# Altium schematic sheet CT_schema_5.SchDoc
size 368 x 245 mm
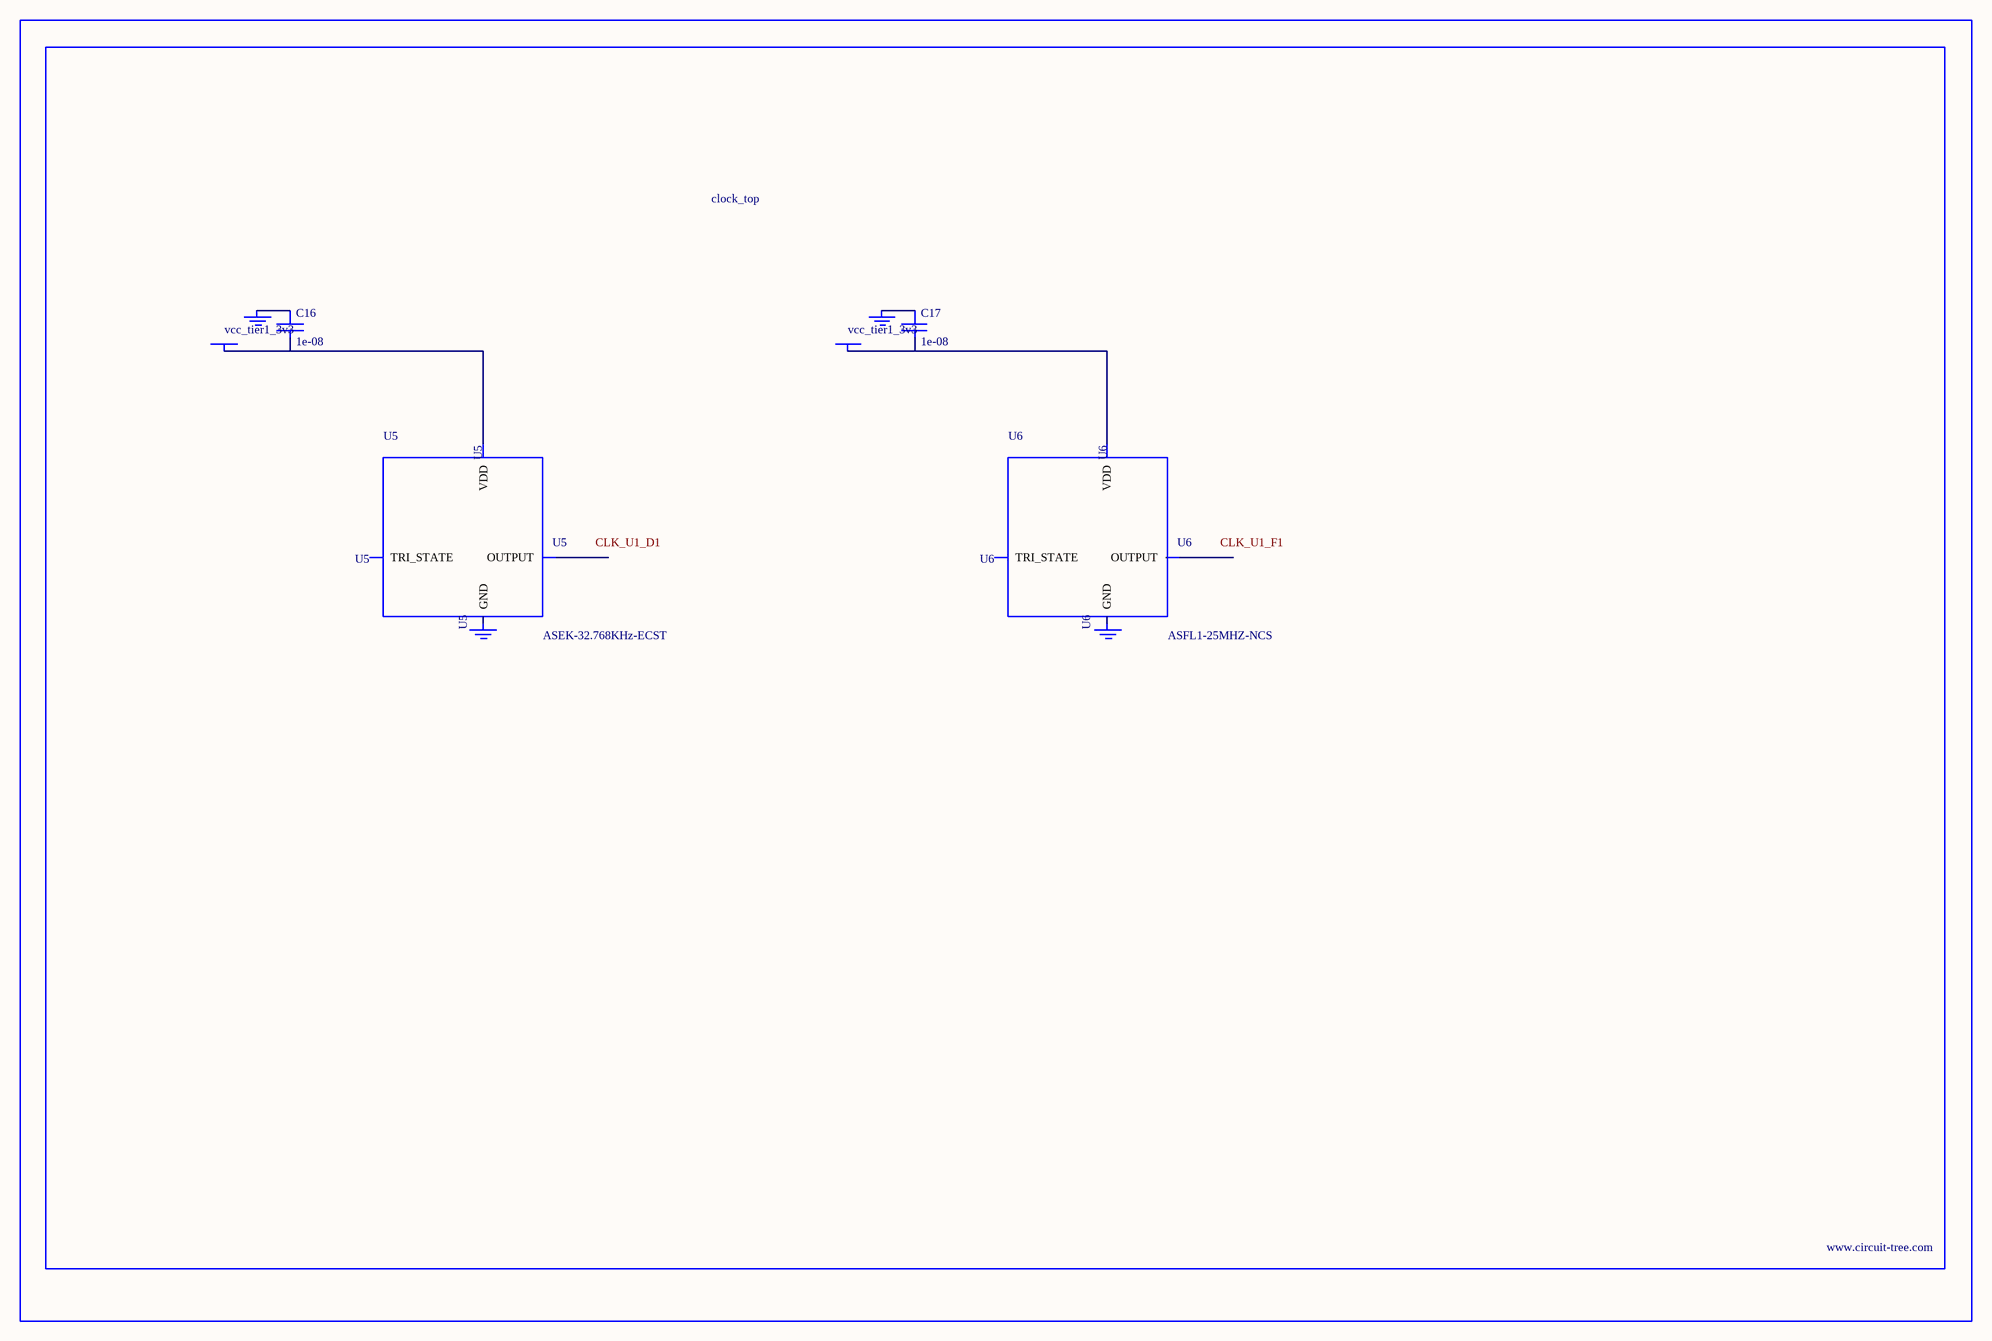
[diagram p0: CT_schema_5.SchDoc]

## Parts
BORDER4  (no value)
C16  1e-08  [C0402]
C17  1e-08  [C0402]
GND_INSTANCE_4_0  (no value)
GND_INSTANCE_4_1  (no value)
GND_INSTANCE_4_2  (no value)
GND_INSTANCE_4_3  (no value)
POWER_INSTANCE_4_0  vcc_tier1_3v3
POWER_INSTANCE_4_1  vcc_tier1_3v3
U5  ASEK-32.768KHz-ECST  [ASEK]
U6  ASFL1-25MHZ-NCS  [ASFL1]

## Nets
NetC16_1: C16.1 GND_INSTANCE_4_0.0(GND)
NetC16_2: C16.2 POWER_INSTANCE_4_0.0(PWR) U5.4(VDD)
NetC17_1: C17.1 GND_INSTANCE_4_2.0(GND)
NetC17_2: C17.2 POWER_INSTANCE_4_1.0(PWR) U6.4(VDD)

Not connected (* = marked no-connect by the designer): GND_INSTANCE_4_1 0(GND); GND_INSTANCE_4_3 0(GND); U5 1(TRI_STATE) 2(GND) 3(OUTPUT); U6 1(TRI_STATE) 2(GND) 3(OUTPUT)

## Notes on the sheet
- Labels drawn without touching a wire or pin: CLK_U1_D1, CLK_U1_F1

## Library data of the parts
BORDER4 = BORDER_PAGE4
C16 C17 = C0402C103K3RAC
GND_INSTANCE_4_0-GND_INSTANCE_4_3 = GND
POWER_INSTANCE_4_0 POWER_INSTANCE_4_1 = PWR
